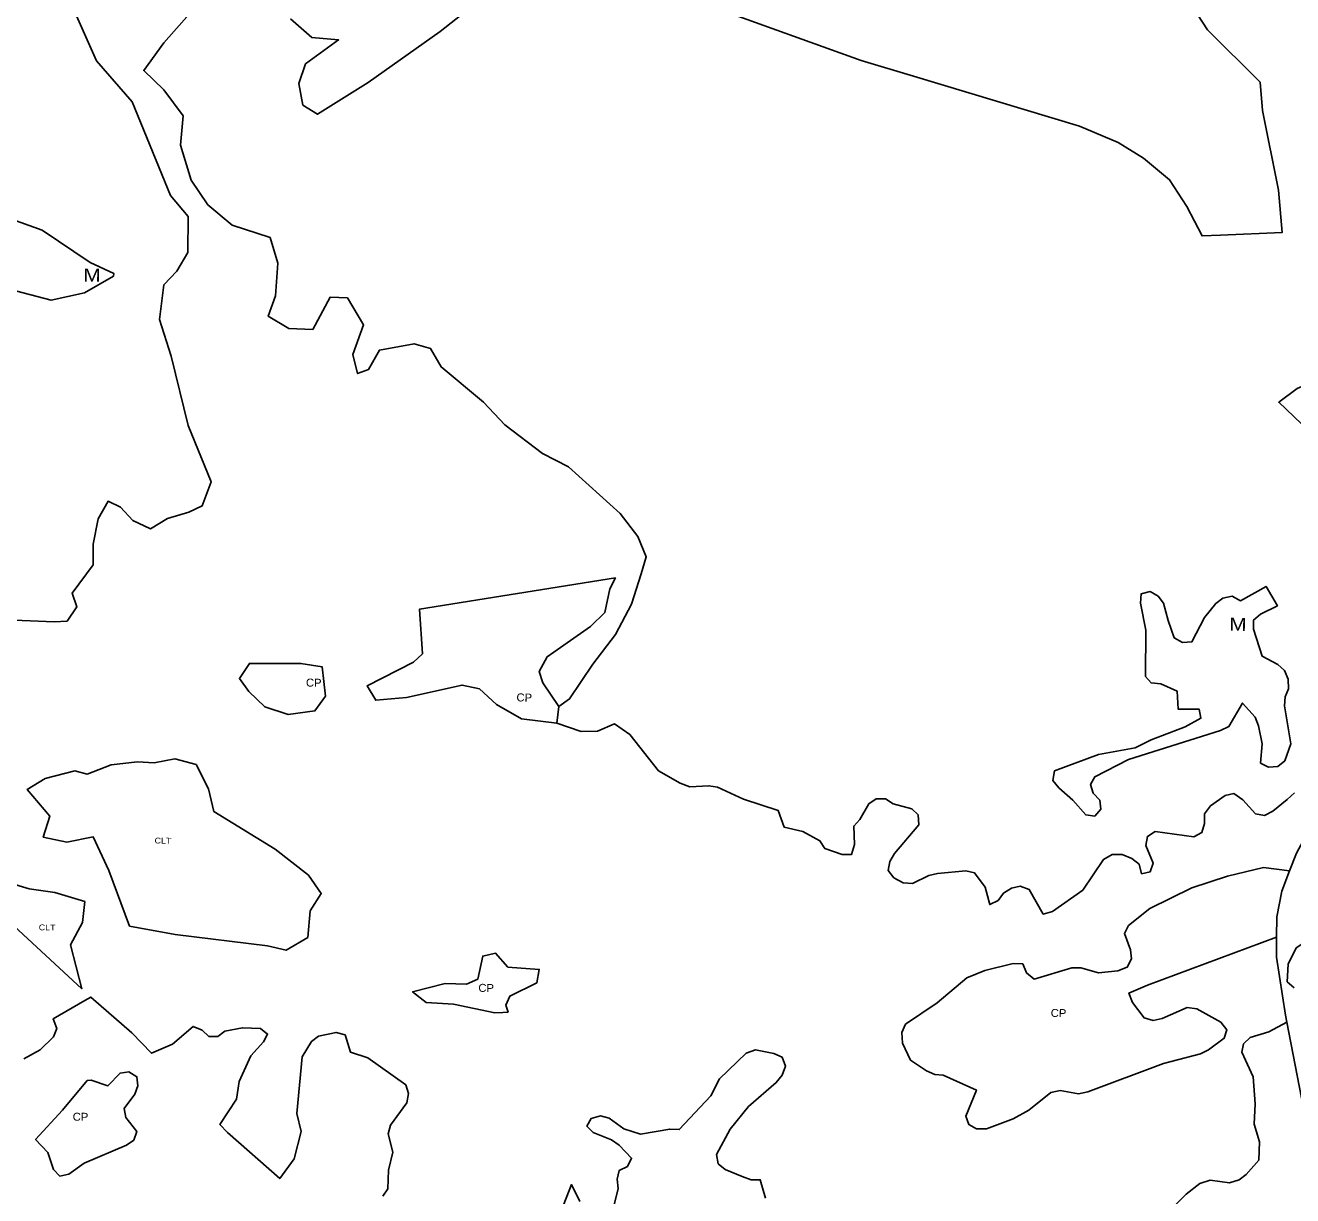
# Model space of a CAD drawing. Extents: x 713589 to 726391, y 7177764 to 7191819.
# Drawn here: x 716445 to 717458, y 7181536 to 7182472 of the extents above; entities that cross this region are included whole.
import ezdxf
from ezdxf.enums import TextEntityAlignment as Align

# ---------------------------------------------------------------- set-up
doc = ezdxf.new("R2010")
doc.units = 0
doc.header["$LTSCALE"] = 2.6
doc.layers.add('63', color=7, linetype='Continuous', lineweight=25)

msp = doc.modelspace()

# ---------------------------------------------------------------- linework, layer by layer
at = {"layer": '63'}
msp.add_line((716871.56, 7181927.28), (716869.84, 7181913.83), dxfattribs=at)
for points in [[(716459.93, 7182537.62), (716501.5, 7182443.83), (716530.17, 7182410.95), (716560.83, 7182336), (716574.83, 7182319.22), (716574.78, 7182290.48), (716565.86, 7182275.45), (716555.58, 7182264.52), (716552.12, 7182236.82), (716561.3, 7182207.39), (716574.89, 7182151.96), (716593.29, 7182106.79), (716586.14, 7182087.78), (716575.53, 7182082.67), (716558.42, 7182077.56), (716544.73, 7182069.38), (716530.71, 7182075.9), (716520.81, 7182086.52), (716510.9, 7182091.32), (716503.01, 7182077.31), (716498.87, 7182057.14), (716498.85, 7182040.38), (716482.05, 7182017.84), (716485.79, 7182006.88), (716478.02, 7181995.47), (716467.72, 7181994.81), (716416.39, 7181997.1)], [(716656.68, 7182477.28), (716673.81, 7182462.4), (716695.25, 7182460.39), (716668.82, 7182441.3), (716663.52, 7182425.48), (716666.79, 7182408.32), (716678.32, 7182401.04), (716718.94, 7182426.37), (716776.41, 7182467.18), (716797.88, 7182483.97)], [(716981.28, 7182491.42), (717113.23, 7182444.01), (717155.28, 7182431.33), (717287.96, 7182391.33), (717318.89, 7182378.49), (717339.29, 7182365.98), (717360.02, 7182348.54), (717373.83, 7182327.15), (717386.03, 7182303.63), (717400.73, 7182304.28), (717450.23, 7182306.45), (717447.22, 7182340.23), (717434.41, 7182404), (717432.43, 7182426.78), (717390.31, 7182468.58), (717382.42, 7182480.76)], [(716871.56, 7181927.28), (716880.09, 7181933.27), (716898.61, 7181960.95), (716916.79, 7181984.67), (716929.7, 7182009.06), (716937.21, 7182033.35), (716941.36, 7182046.77), (716934.74, 7182063.15), (716920.58, 7182081.65), (716879.24, 7182118.97), (716858.4, 7182129.6), (716828.34, 7182152.57), (716811.26, 7182170.73), (716777.45, 7182198.83), (716768.92, 7182213.55), (716755.59, 7182217.33), (716727.88, 7182212.25), (716719.3, 7182196.87), (716710.4, 7182193.47), (716706.67, 7182208.86), (716715.26, 7182232.45), (716702.3, 7182254.02), (716688.62, 7182254.73), (716674.55, 7182228.75), (716655.4, 7182229.47), (716639, 7182239.42), (716644.84, 7182255.82), (716646.59, 7182281.82), (716640.47, 7182302.35), (716610.04, 7182312.32), (716590.58, 7182328.42), (716577.27, 7182348.28), (716568.77, 7182376.34), (716570.86, 7182399.6), (716555.5, 7182420.49), (716539.45, 7182435.91), (716555.56, 7182458.11), (716577.84, 7182483.38)], [(716869.84, 7181913.83), (716841.47, 7181917.17), (716821.7, 7181928.75), (716807.86, 7181941.31), (716794.01, 7181944.3), (716749.46, 7181934.48), (716725.05, 7181932.21), (716718.14, 7181943.77), (716755.12, 7181962.51), (716762.39, 7181969.42), (716760.08, 7182005.13), (716916.69, 7182030.08), (716912.24, 7182021.3), (716908.25, 7182002.5), (716896.68, 7181991.3), (716862, 7181966.95), (716855.72, 7181955.08), (716858.67, 7181946.17), (716871.56, 7181927.28)], [(716869.84, 7181913.83), (716889.29, 7181907.2), (716902.48, 7181907.5), (716916.02, 7181913.42), (716928.21, 7181904.82), (716951.25, 7181875.76), (716968.39, 7181865.83), (716976.37, 7181862.83), (716991.5, 7181863.82), (716998.41, 7181862.5), (717019.14, 7181852.95), (717046.79, 7181844.06), (717051.72, 7181830.57), (717066.53, 7181827.28), (717080.35, 7181819.71), (717084.29, 7181813.45), (717098.11, 7181808.84), (717105.68, 7181808.84), (717107.99, 7181816.74), (717107.33, 7181831.55), (717112.27, 7181836.81), (717119.51, 7181849.32), (717125.43, 7181853.26), (717132.67, 7181853.26), (717138.93, 7181849.31), (717153.73, 7181845.36), (717159, 7181840.42), (717159.33, 7181832.53), (717139.91, 7181809.5), (717136.28, 7181803.24), (717134.97, 7181796), (717139.57, 7181790.08), (717146.81, 7181786.13), (717154.38, 7181785.47), (717167.54, 7181792.05), (717174.46, 7181793.69), (717197.16, 7181795.66), (717204.07, 7181794.02), (717212.63, 7181782.5), (717216.24, 7181768.68), (717222.83, 7181771.97), (717227.1, 7181777.89), (717233.69, 7181781.84), (717240.6, 7181783.48), (717247.84, 7181780.85), (717259.02, 7181761.1), (717266.26, 7181763.07), (717290.61, 7181780.18), (717307.07, 7181804.86), (717313.98, 7181808.81), (717322.21, 7181808.81), (717329.78, 7181805.51), (717335.7, 7181800.91), (717337.67, 7181793.34), (717344.59, 7181794.98), (717346.89, 7181801.89), (717340.97, 7181816.04), (717342.29, 7181823.28), (717348.54, 7181827.23), (717379.47, 7181822.95), (717385.72, 7181826.23), (717388.03, 7181833.47), (717388.03, 7181841.37), (717392.64, 7181847.62), (717404.49, 7181855.85), (717411.4, 7181857.49), (717418.64, 7181852.55), (717428.84, 7181841.36), (717436.07, 7181840.05), (717442.66, 7181843.34), (717454.18, 7181852.88), (717460.1, 7181858.14)], [(717454.15, 7181706.77), (717454.81, 7181720.92), (717461.39, 7181734.08), (717479.5, 7181745.93), (717493.97, 7181744.94), (717500.89, 7181748.55), (717503.52, 7181755.14), (717501.22, 7181762.05), (717495.62, 7181767.64), (717489.7, 7181771.59), (717475.22, 7181776.2), (717469.3, 7181780.15), (717466.34, 7181786.73), (717466.01, 7181793.97), (717466.32, 7181794.28), (717471.28, 7181799.24), (717477.53, 7181803.51), (717497.93, 7181811.74), (717500.9, 7181818.32), (717496.29, 7181824.9), (717490.7, 7181829.51), (717475.85, 7181836.5), (717461.61, 7181809.77), (717456.05, 7181795.59)], [(717456.05, 7181795.59), (717435.08, 7181798.26), (717406.45, 7181791.35), (717377.82, 7181782.14), (717344.25, 7181765.69), (717327.14, 7181751.88), (717323.84, 7181745.62), (717328.78, 7181732.46), (717329.44, 7181725.22), (717326.14, 7181718.64), (717318.57, 7181715.68), (717303.11, 7181714.04), (717288.96, 7181717.99), (717281.72, 7181717.99), (717251.77, 7181709.11), (717245.52, 7181714.05), (717242.56, 7181721.29), (717234.99, 7181721.62), (717212.28, 7181716.03), (717197.8, 7181710.11), (717174.11, 7181690.04), (717148.77, 7181672.93), (717145.8, 7181666.35), (717146.46, 7181657.79), (717152.71, 7181644.3), (717165.54, 7181635.74), (717172.12, 7181632.78), (717178.9, 7181632.12), (717205.55, 7181620.24), (717197.13, 7181599.54), (717199.43, 7181592.63), (717205.68, 7181589.34), (717213.58, 7181589.33), (717234.97, 7181597.23), (717247.48, 7181604.14), (717264.92, 7181618.28), (717272.49, 7181619.93), (717287.3, 7181617.29), (717294.54, 7181618.94), (717355.09, 7181641.63), (717384.71, 7181649.2), (717391.29, 7181652.48), (717403.79, 7181661.7), (717405.77, 7181668.61), (717401.16, 7181674.53), (717381.75, 7181685.39), (717374.18, 7181686.38), (717354.11, 7181677.5), (717346.87, 7181675.86), (717339.63, 7181678.16), (717330.42, 7181690.34), (717327.57, 7181697.94), (717342.46, 7181704.16), (717445.63, 7181742.59)], [(717456.05, 7181795.59), (717449.75, 7181779.5), (717445.8, 7181758.76), (717445.63, 7181742.59)], [(717445.63, 7181742.59), (717445.47, 7181726.52), (717452.7, 7181680.12), (717453.79, 7181674.5)], [(717459.74, 7181702.16), (717454.15, 7181706.77)], [(716624.95, 7181647.69), (716635.2, 7181658.89), (716638.51, 7181665.15), (716632.91, 7181669.45), (716618.39, 7181670.13), (716604.21, 7181667.52), (716598.59, 7181663.24), (716591.33, 7181663.25), (716586.06, 7181668.21), (716578.81, 7181671.19), (716562.29, 7181657.03), (716545.48, 7181649.75), (716529.84, 7181666.02), (716497.04, 7181694.71), (716492.16, 7181691.9), (716466.99, 7181677.41), (716469.76, 7181669.48), (716467.09, 7181662.85), (716456.47, 7181652.6), (716443.54, 7181645.33)], [(717340.91, 7181504.41), (717373.17, 7181536.98), (717384.36, 7181545.54), (717392.59, 7181548.17), (717408.05, 7181546.19), (717415.62, 7181548.49), (717421.22, 7181552.77), (717431.42, 7181564.29), (717432.08, 7181578.77), (717427.8, 7181592.92), (717428.47, 7181609.37), (717426.82, 7181630.76), (717417.94, 7181650.51), (717419.26, 7181657.42), (717424.53, 7181662.35), (717439.33, 7181666.96), (717453.79, 7181674.5)], [(717453.79, 7181674.5), (717467.16, 7181605.74), (717487.55, 7181528.74), (717522.09, 7181465.22), (717539.53, 7181443.83), (717555.98, 7181430.66), (717606.98, 7181404.99), (717635.61, 7181384.91), (717646, 7181374.88)], [(716730.66, 7181535.36), (716734.63, 7181541.29), (716735.31, 7181556.13), (716738.63, 7181570.64), (716735.03, 7181585.16), (716736.69, 7181592.09), (716749.92, 7181610.21), (716751.25, 7181617.46), (716748.95, 7181624.4), (716718.64, 7181646.22), (716704.79, 7181650.53), (716700.52, 7181664.39), (716693.27, 7181666.38), (716679.08, 7181663.44), (716673.47, 7181659.16), (716666.19, 7181646.96), (716661.82, 7181601.45), (716665.43, 7181587.26), (716659.78, 7181565.17), (716648.21, 7181549.45), (716606.31, 7181586.48), (716600.34, 7181592.69), (716613.68, 7181613.07), (716615.68, 7181627.26), (716624.95, 7181647.69)], [(717036.86, 7181533.75), (717032.58, 7181548.56), (717025.34, 7181548.56), (717018.1, 7181551.2), (717004.61, 7181556.79), (716999.02, 7181561.4), (716997.71, 7181568.64), (717008.57, 7181589.04), (717023.05, 7181607.14), (717045.43, 7181626.22), (717050.04, 7181632.14), (717052.67, 7181639.38), (717050.04, 7181646.62), (717043.46, 7181649.58), (717028.65, 7181652.55), (717021.41, 7181649.92), (717000.02, 7181629.19), (716993.11, 7181615.7), (716967.76, 7181588.72), (716960.19, 7181589.05), (716936.83, 7181585.11), (716923.34, 7181589.39), (716911.82, 7181597.94), (716904.91, 7181599.59), (716897.34, 7181597.62), (716893.72, 7181591.37), (716898.99, 7181586.43), (716913.47, 7181580.5), (716919.72, 7181576.22), (716929.59, 7181565.69), (716926.3, 7181559.11), (716919.71, 7181555.82), (716918.07, 7181548.91), (716919.05, 7181541.67), (716915.43, 7181527.52)], [(716888.12, 7181531.15), (716881.54, 7181544.64), (716872.98, 7181522.92)]]:
    msp.add_lwpolyline(points, dxfattribs=at)
for points in [[(716340.89, 7182326.79), (716360.07, 7182342.49), (716395.98, 7182338.67), (716423.65, 7182320.49), (716458.18, 7182308.12), (716496.44, 7182282.41), (716515.58, 7182273.48), (716515.16, 7182271.49), (716491.96, 7182258.13), (716465.27, 7182252.36), (716431.76, 7182260.97), (716409.55, 7182274.34), (716399.67, 7182293.17), (716378.49, 7182309.96), (716346.69, 7182314.12)], [(717565.33, 7182192.46), (717567.3, 7182184.89), (717578.49, 7182170.74), (717568.94, 7182164.82), (717512.67, 7182157.59), (717500.5, 7182151.34), (717495.89, 7182130.77), (717491.39, 7182133.44), (717465.63, 7182153.19), (717447.32, 7182170.61), (717462, 7182181.62), (717472.86, 7182186.22), (717487.67, 7182178.32), (717497.21, 7182163.84), (717508.4, 7182163.84), (717519.26, 7182170.09), (717524.53, 7182201.35), (717532.42, 7182204.31)], [(717271.54, 7181862.12), (717266.61, 7181868.05), (717267.93, 7181875.62), (717303.14, 7181888.77), (717332.43, 7181894.03), (717345.26, 7181900.61), (717372.58, 7181910.81), (717385.08, 7181917.72), (717383.77, 7181924.96), (717366.98, 7181924.96), (717366, 7181939.44), (717353.17, 7181945.36), (717345.27, 7181946.02), (717340.66, 7181951.29), (717341, 7181988.15), (717336.73, 7182009.86), (717337.38, 7182017.43), (717344.62, 7182019.08), (717350.88, 7182015.46), (717355.15, 7182009.86), (717358.77, 7181996.04), (717363.7, 7181982.22), (717370.28, 7181978.27), (717377.85, 7181978.92), (717388.06, 7181998.34), (717396.95, 7182009.53), (717402.54, 7182013.8), (717410.11, 7182015.45), (717416.69, 7182011.83), (717437.25, 7182023.19), (717446.26, 7182007.73), (717432.81, 7182000.96), (717427.22, 7181996.36), (717427.22, 7181989.12), (717434.12, 7181967.4), (717446.63, 7181960.81), (717451.89, 7181955.88), (717454.85, 7181948.97), (717455.18, 7181941.4), (717452.54, 7181934.82), (717451.89, 7181927.58), (717457.15, 7181897.3), (717452.21, 7181883.81), (717446.61, 7181879.2), (717439.04, 7181878.55), (717432.79, 7181881.84), (717434.11, 7181897.31), (717431.15, 7181911.79), (717428.52, 7181918.7), (717418.32, 7181929.89), (717407.46, 7181911.13), (717400.88, 7181907.84), (717327.16, 7181884.82), (717300.17, 7181871), (717296.88, 7181864.75), (717298.86, 7181857.84), (717304.12, 7181852.25), (717305.11, 7181845.01), (717300.17, 7181839.41), (717292.93, 7181840.4), (717282.73, 7181852.25)], [(716623.54, 7181939.26), (716615.97, 7181949.5), (716623.91, 7181961.69), (716665.14, 7181961.62), (716682.14, 7181958.78), (716684.89, 7181935.53), (716676.3, 7181923.67), (716654.85, 7181920.74), (716636.39, 7181927.03)], [(716644.45, 7181812.9), (716671.09, 7181792.33), (716681.33, 7181777.61), (716672.41, 7181763.6), (716670.66, 7181742.4), (716653.2, 7181732.17), (716638.5, 7181735.61), (716564.64, 7181744.63), (716528.05, 7181751.53), (716511.37, 7181796.02), (716498.99, 7181822.88), (716477.89, 7181818.65), (716459.03, 7181822.51), (716464.24, 7181839.53), (716446.15, 7181860.77), (716460.53, 7181869.64), (716484.14, 7181875.76), (716494.05, 7181873), (716513.22, 7181880.5), (716534.43, 7181882.86), (716547.77, 7181882.15), (716564.19, 7181885.2), (716581.28, 7181880.73), (716591.17, 7181861.21), (716595.59, 7181843.08)], [(716490.44, 7181754.33), (716480.83, 7181736.56), (716489.78, 7181701.29), (716395.73, 7181788.16), (716411.11, 7181799.34), (716430.98, 7181786.23), (716447.73, 7181781.42), (716468.24, 7181778.3), (716492.17, 7181771.08)], [(716797.66, 7181705.09), (716780.51, 7181705.45), (716754.43, 7181698.89), (716765.31, 7181690.3), (716787.08, 7181688.94), (716820.38, 7181681.96), (716826.52, 7181682.36), (716830.86, 7181682.65), (716829.15, 7181688.35), (716832.28, 7181695.47), (716853.74, 7181705.99), (716855.74, 7181716.87), (716830.67, 7181718.56), (716820.79, 7181729.79), (716810.56, 7181727.5), (716806.57, 7181709.03)], [(716523.67, 7181605.43), (716532.31, 7181617.01), (716534.64, 7181623.64), (716533.99, 7181630.93), (716527.37, 7181634.92), (716520.4, 7181633.93), (716510.78, 7181623.68), (716497.2, 7181628.34), (716494.16, 7181628.01), (716474.52, 7181604.2), (716452.81, 7181580.75), (716462.63, 7181570.4), (716467.25, 7181556.8), (716472.21, 7181551.49), (716479.51, 7181553.14), (716491.78, 7181561.73), (716525.61, 7181576.26), (716531.58, 7181580.23), (716533.91, 7181587.18), (716524.99, 7181598.46)]]:
    msp.add_lwpolyline(points, close=True, dxfattribs=at)

# ---------------------------------------------------------------- texts
for s, height, width, p in [('M', 10.4, 1.2, (716497.89, 7182267.06)), ('M', 10.4, 1.2, (717414.62, 7181987.73)), ('CP', 6.4, 1.05, (716675.35, 7181943.02)), ('CP', 6.4, 1.05, (716843.77, 7181931.17)), ('CLT', 4.64, 1.15, (716554.75, 7181817.53)), ('CLT', 4.64, 1.15, (716462.1, 7181748.06)), ('CP', 6.4, 1.05, (716813.27, 7181698.81)), ('CP', 6.4, 1.05, (717271.17, 7181678.73)), ('CP', 6.4, 1.05, (716488.75, 7181595.74))]:
    msp.add_text(s, height=height, rotation=359.062, dxfattribs=dict(at, width=width)).set_placement(p, align=Align.CENTER)

doc.saveas('drawing.dxf')
